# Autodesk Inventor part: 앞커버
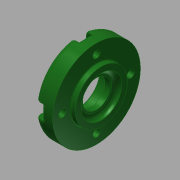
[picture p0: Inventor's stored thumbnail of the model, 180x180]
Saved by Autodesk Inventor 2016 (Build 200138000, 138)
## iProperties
Created: 2015-11
Part Number: 앞커버
Material: 알루미늄 6061
Document SubType Name: Modeling
Designer: mduedu
Density: 1 g/cm^3
Appearance: 매끄러움 - 짙은 산림 녹색
Author: mduedu
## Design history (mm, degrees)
sketch "스케치1"
  geometry: L1 (-7, 0)-(7, 0); L2 (-7, 0)-(-7, 27); L3 (-7, 27)-(4, 27); L4 (4, 27)-(4, 16); L5 (4, 16)-(7, 16); L6 (7, 16)-(7, 0); 2 further points
  constraints: 12 end point, 3 perpendicular, 2 parallel, 1 coincident, 1 horizontal, 1 midpoint
  dimensions: "d0" = 14 distance of L1.start L1.end; "d1" = 54 diameter of L3 L1; "d2" = 3 distance of L4.end L5.end; "d3" = 32 diameter of L5 L1
revolve "회전1" sketch "스케치1" stored, may be unused: angle "d4" = 90 deg
hole "구멍1" diameter "d7" = 25; stored, may be unused: countersink angle "d11" = 90 deg, drill point angle "d13" = 0 deg; dims "d5" = 10, "d6" = 10, "d8" = 6, "d9" = 4, "d10" = 2, "d12" = 3
hole "구멍2" diameter "d16" = 25; stored, may be unused: countersink angle "d20" = 90 deg, drill point angle "d22" = 0 deg; dims "d17" = 6, "d18" = 4, "d19" = 2, "d21" = 7.7, "d58" = 10, "d59" = 10
hole "구멍3" diameter "d25" = 17; stored, may be unused: countersink angle "d29" = 90 deg, drill point angle "d31" = 0 deg; dims "d23" = 10, "d24" = 10, "d26" = 6, "d27" = 4, "d28" = 2, "d30" = 4.2
chamfer "모따기1" distance "d32" = 0.6; stored, may be unused: second distance "d33" = 2, angle "d34" = 30 deg
fillet "모깎기1" dims "d35" = 0.3
fillet "모깎기2" dims "d36" = 3
fillet "모깎기3" dims "d37" = 3
fillet "모깎기4" dims "d38" = 0.3
sketch "스케치3" dims "d61" = 42
  geometry: C1 r 27 at (0, 0) reference; 2 further points
  constraints: 2 vertical alignment, 1 coincident, 2 other
hole "구멍4" sketch "스케치3" at (0, 21) diameter "d44" = 4.5; stored, may be unused: countersink angle "d48" = 90 deg, drill point angle "d50" = 0 deg; dims "d45" = 6, "d46" = 8, "d47" = 4.6, "d49" = 8
sketch "스케치4"
  geometry: L1 (-4, 5.702)-(-4, 0); L2 (4, 5.702)-(4, 0); A1 r 27 centre (0, -21) between (-4, 5.702) and (4, 5.702) reference; A2 r 4 centre (0, 0) between (-2.824, 2.833) and (2.824, 2.833) reference
  constraints: 4 end point, 4 point on circle, 2 tangent, 2 vertical
extrude "돌출1" cut sketch "스케치4" stored distance "d51" = 0; taper "d52" = 0 deg
fillet "모깎기5" dims "d56" = 0.3
fillet "모깎기6" dims "d57" = 1
node "솔리드1"
pattern_circular "원형 패턴2" dims angle "d64" = 360 deg
pattern_circular "원형 패턴1" dims angle "d54" = 360 deg
